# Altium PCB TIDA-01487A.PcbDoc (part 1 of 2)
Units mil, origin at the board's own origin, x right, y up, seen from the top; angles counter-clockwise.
Board outline 3500 x 2800 mil, 4 copper layers (Top Layer, GND, VDD, Bottom Layer), stack 61.6 mil thick; 82 components, 45 nets, 239 pads, 112 vias.
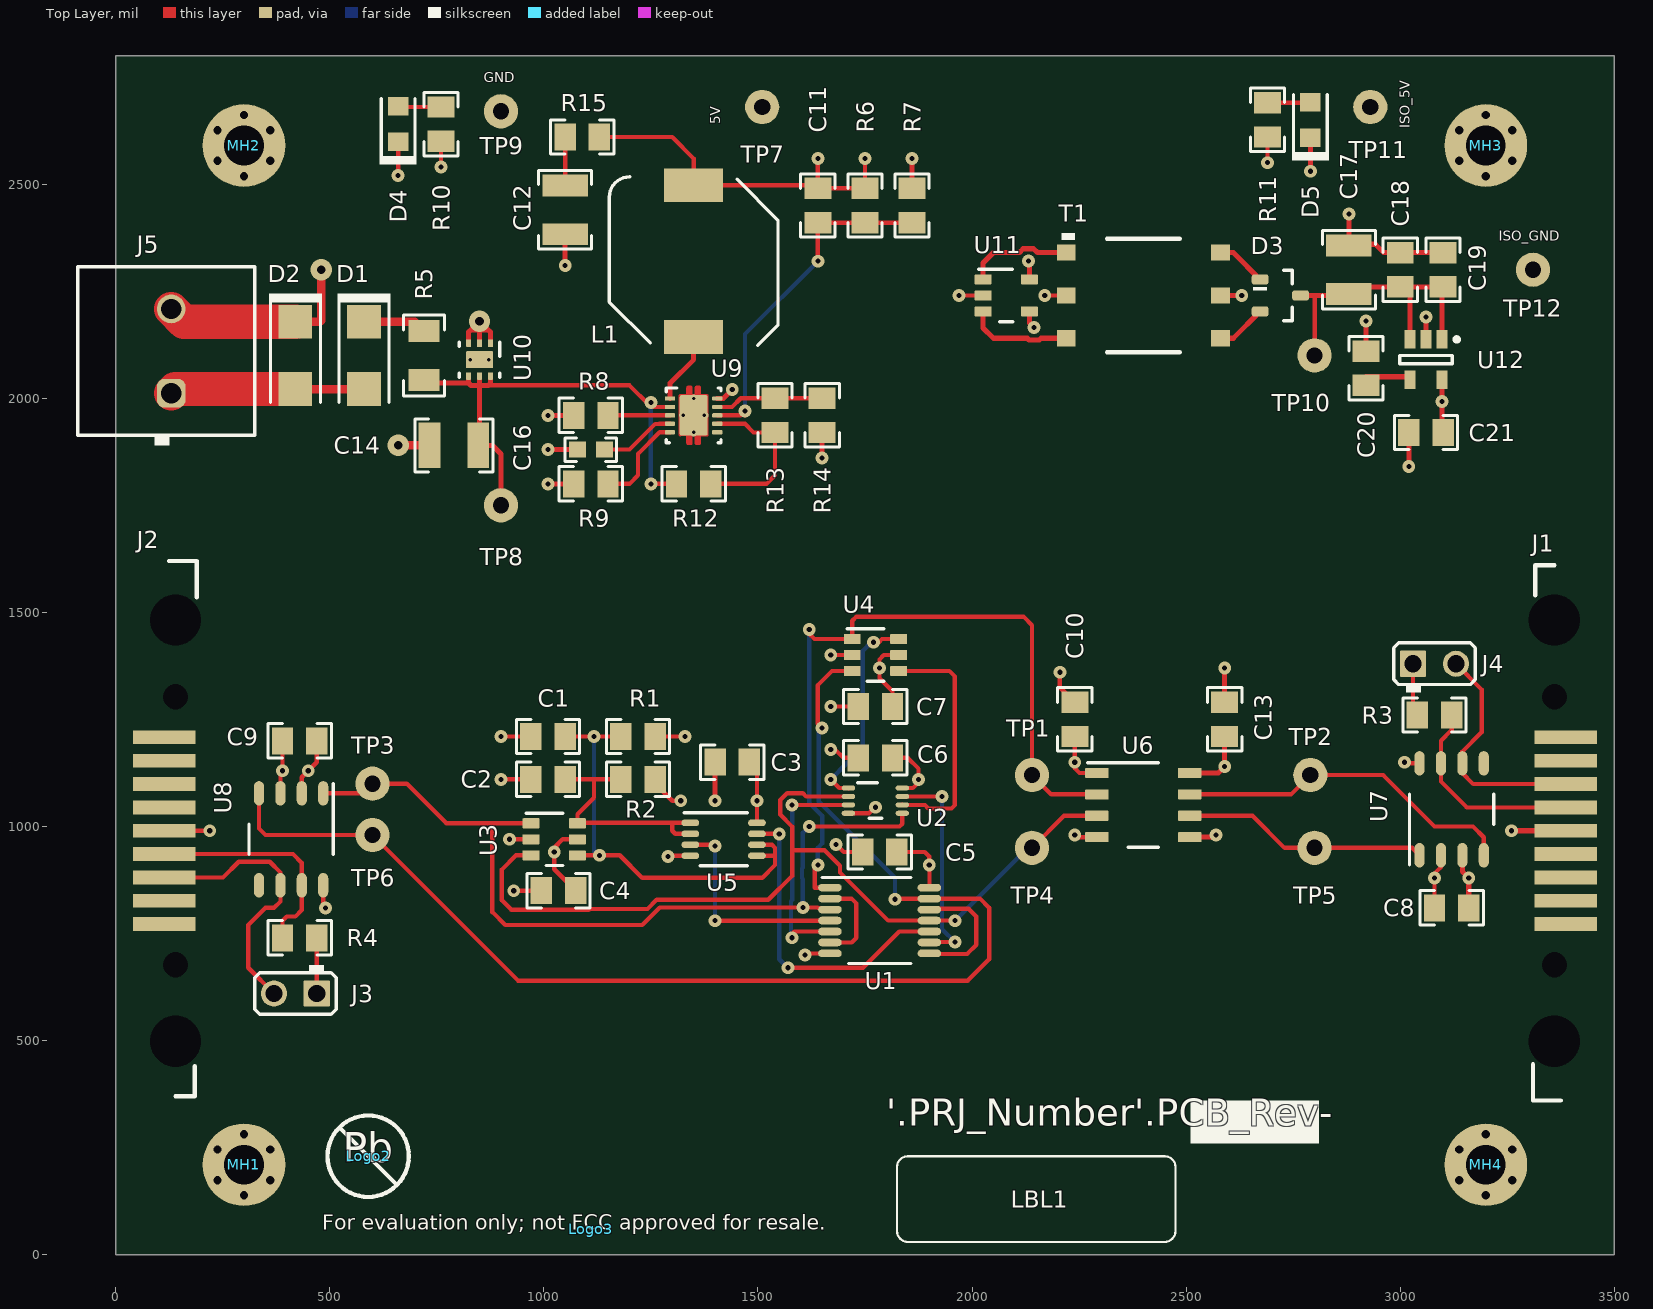
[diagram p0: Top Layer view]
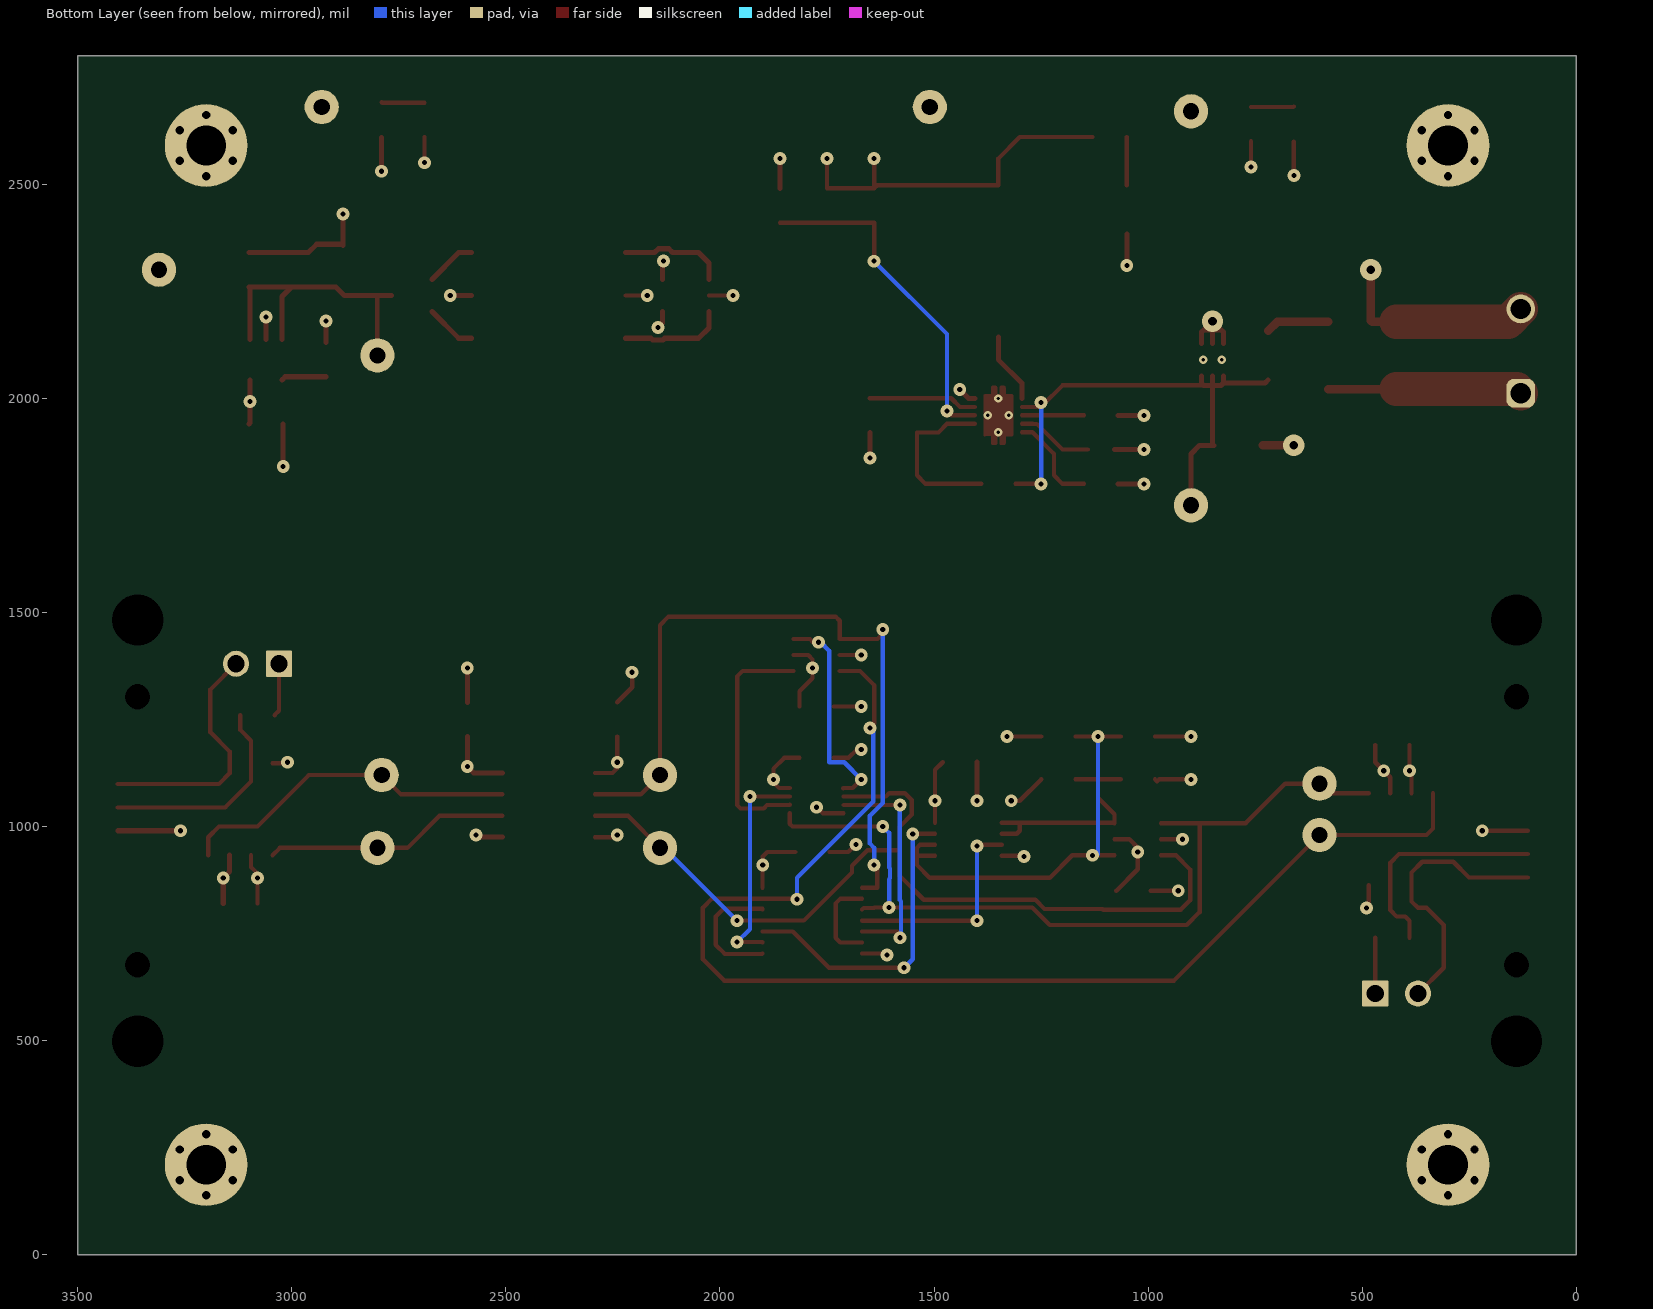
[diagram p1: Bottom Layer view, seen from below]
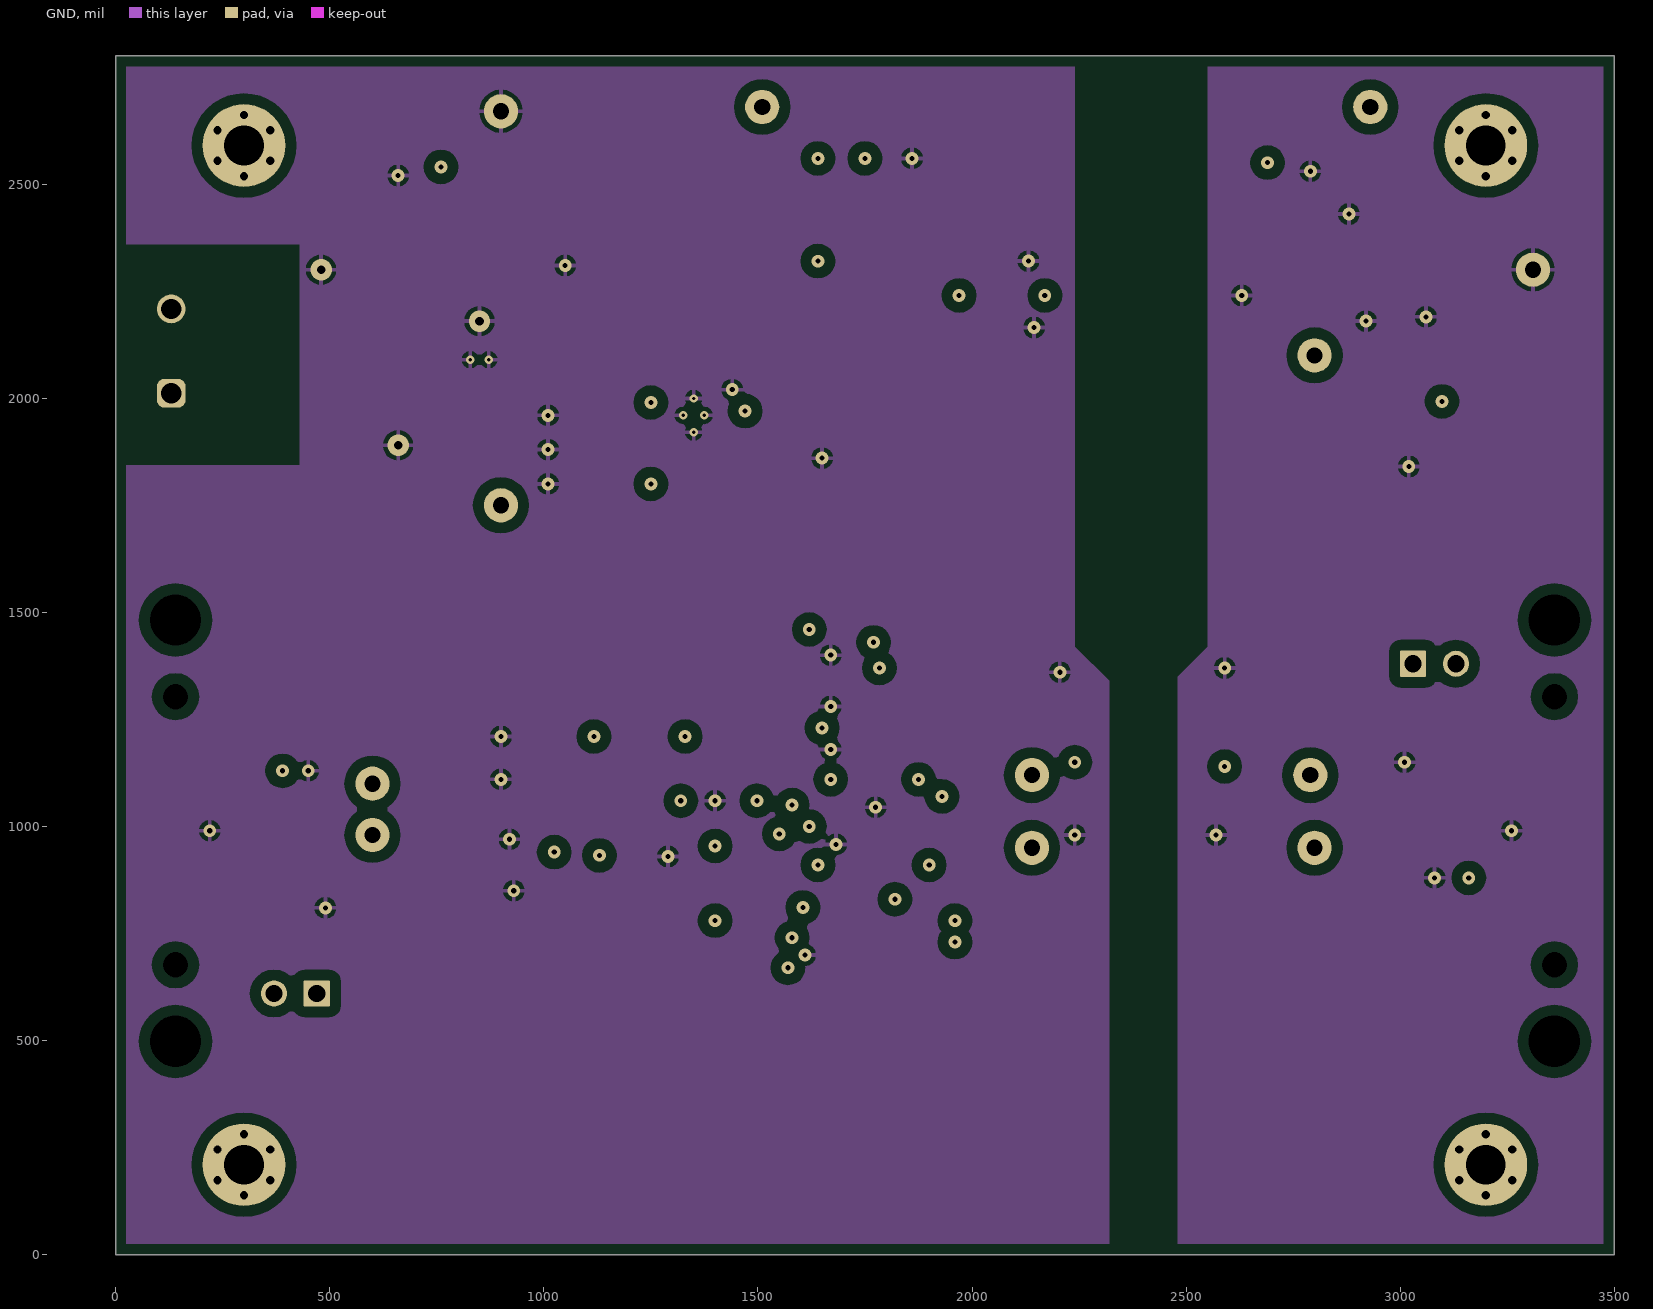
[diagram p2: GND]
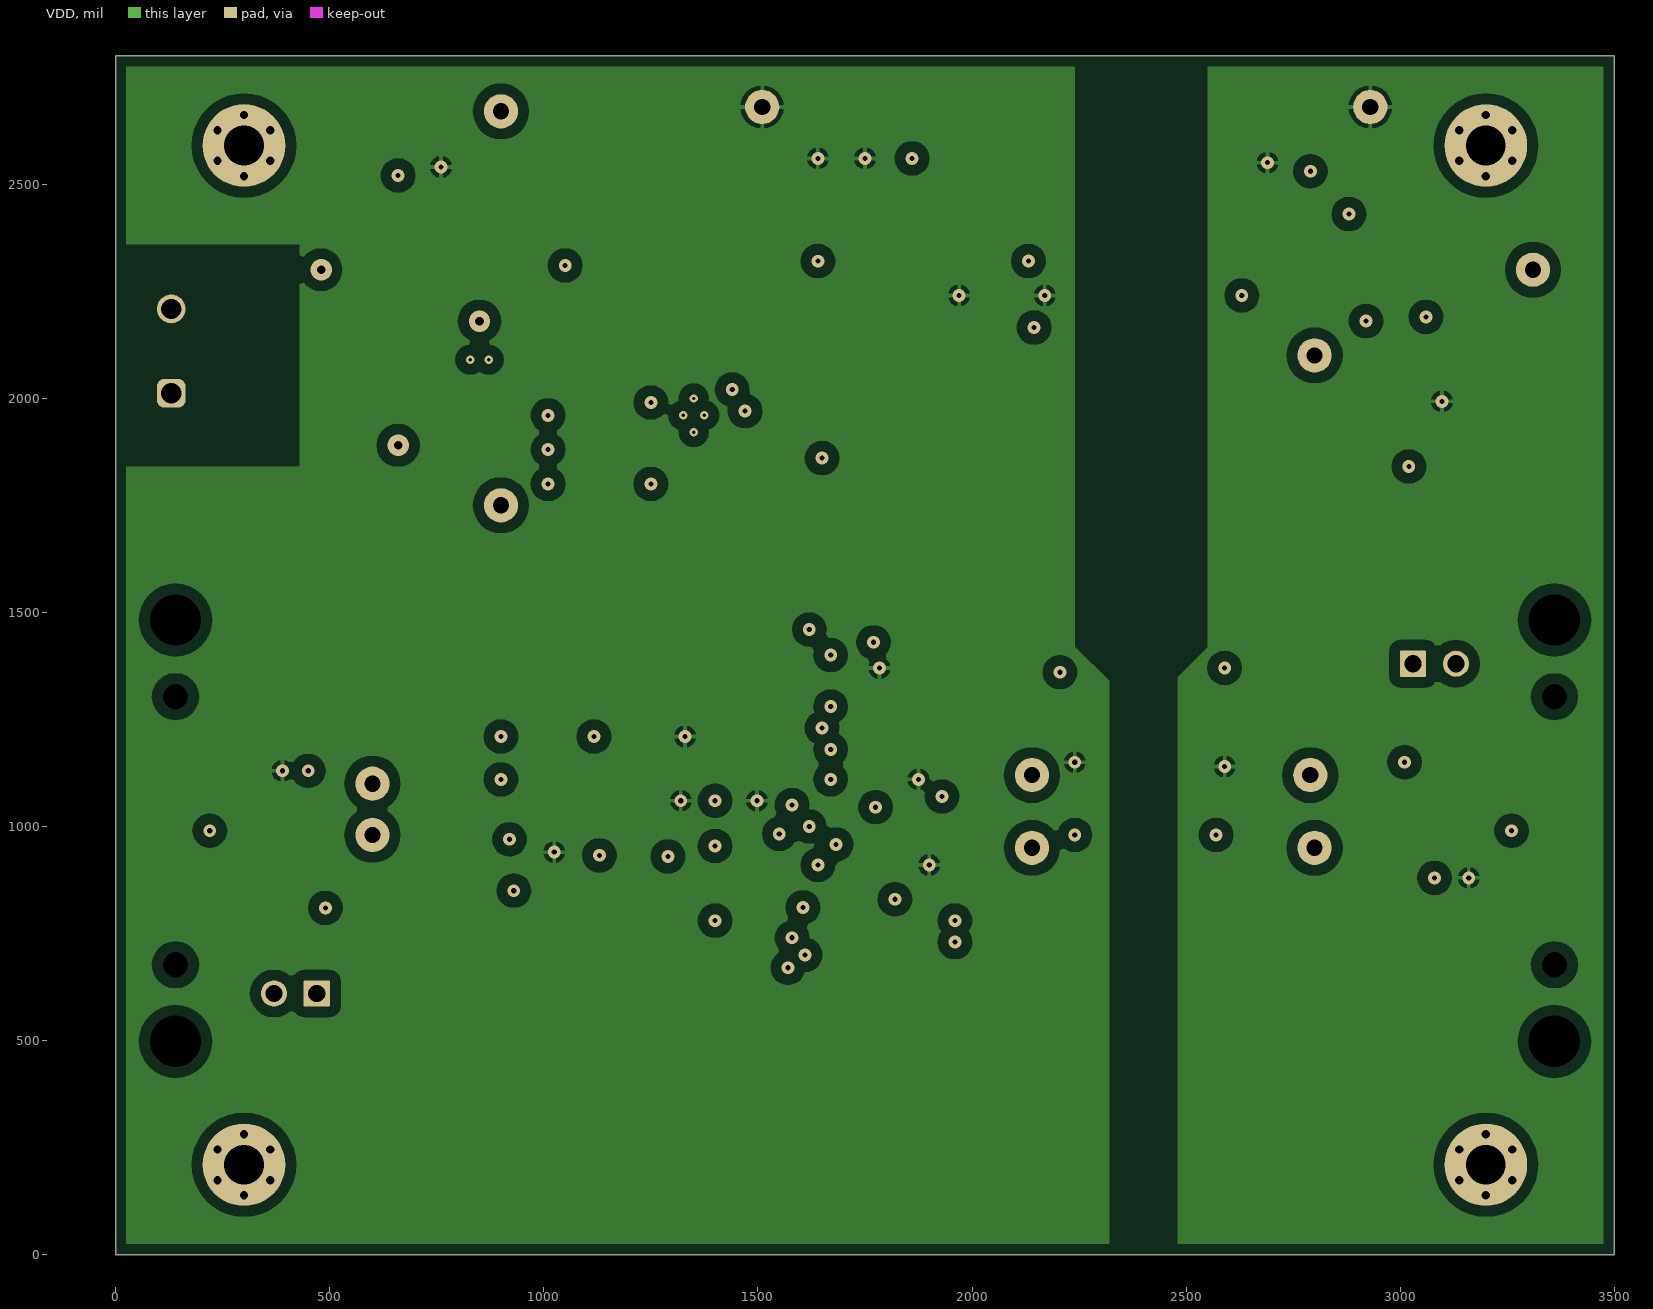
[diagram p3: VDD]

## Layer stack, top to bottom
Top Solder: solder mask 0.4, Solder Resist, Dk 3.5
Top Layer: signal copper 1.4
Dielectric1: core 8, FR-4, Dk 4.8
GND: signal copper 1.4
Dielectric 2: dielectric 40, FR-4, Dk 4.2
VDD: signal copper 1.4
Dielectric 3: dielectric 8, Dk 4.2
Bottom Layer: signal copper 1.4
Bottom Solder: solder mask 0.4, Solder Resist, Dk 3.5

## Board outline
0,0 3500,0 3500,430 3500,860 3500,1720 3500,2800 0,2800

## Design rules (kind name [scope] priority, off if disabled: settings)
AcuteAngle [All] p1: minimum=4.50000000000000E+0001 checktracksonly=FALSE
AssemblyTestPointUsage [All] p1: valid=2
BoardOutlineClearance BoardOutlineClearance_MountingHoles [OnCopper and InComponentClass('Mounting Holes')] p1: gap=40 ignorepadtopadclearanceinfootprint=FALSE
BoardOutlineClearance BoardOutlineClearance_Poly [OnCopper and IsPoly] p2: gap=25 ignorepadtopadclearanceinfootprint=FALSE
BoardOutlineClearance [OnCopper and Not InComponentClass('Logo') and not InComponentClass('FiducialMark') and not InRegion(1000,500,4000,800) and not InPoly] p3: gap=40 ignorepadtopadclearanceinfootprint=FALSE
Clearance Clearance_Keepouts [((IsTrack Or IsArc) And Not InPoly) And IsFree and IsKeepOut vs ((IsTrack Or IsArc) And Not InPoly) And IsFree and IsKeepOut] p1: gap=0 ignorepadtopadclearanceinfootprint=FALSE
Clearance Clearance_Poly [InPolygon] p2: gap=25 ignorepadtopadclearanceinfootprint=FALSE except(0: Arc-Hole Track-Hole SMDPad-Hole THPad-Hole Via-Hole Fill-Hole Poly-Hole Region-Hole Text-Hole)
Clearance [All] p3: gap=7.87 ignorepadtopadclearanceinfootprint=FALSE except(0: Arc-Hole Track-Hole SMDPad-Hole THPad-Hole Via-Hole Fill-Hole Poly-Hole Region-Hole Text-Hole)
ComponentClearance ComponentClearance_MountingHoles_FiducialMarks [InComponentClass('Mounting Holes') vs InComponentClass('FiducialMark')] p1: gap=50 collisioncheckmode=3 verticalgap=10 showdistances=FALSE
ComponentClearance ComponentClearance_Shunt [InComponentClass('Header') vs InComponentClass('Shunt')] p2: gap=0 collisioncheckmode=3 verticalgap=0 showdistances=FALSE
ComponentClearance ComponentClearance_Logo [InComponentClass('Logo')] p3: gap=50 collisioncheckmode=3 verticalgap=10 showdistances=FALSE
ComponentClearance ComponentClearance_ScrewToNut [(HasFootprint('NY PMS 440 0025 PH')) vs (HasFootprint('Keystone_1902C'))] p4: gap=5 collisioncheckmode=3 verticalgap=10 showdistances=FALSE
ComponentClearance ComponentClearance_MountingHoles [InComponentClass('Mounting Holes')] p5: gap=250 collisioncheckmode=3 verticalgap=100000 showdistances=FALSE
ComponentClearance ComponentClearance_SmallPassives [HasFootprint('0201*') or HasFootprint('0402*') or HasFootprint('0508') or HasFootprint('0603*') or HasFootprint('0612') or HasFootprint('0805*') or HasFootprint('0815*') or HasFootprint('0830*') or HasFootprint('1206*') or HasFootprint('1210*') or HasFootprint('1808*') or HasFootprint('1812*') or HasFootprint('1825*') or HasFootprint('2010*') or HasFootprint('2220*') or HasFootprint('2225*') or HasFootprint('2512*') or HasFootprint('2728*') or HasFootprint('3518*') vs HasFootprint('0201*') or HasFootprint('0402*') or HasFootprint('0508') or HasFootprint('0603*') or HasFootprint('0612') or HasFootprint('0805*') or HasFootprint('0815*') or HasFootprint('0830*') or HasFootprint('1206*') or HasFootprint('1210*') or HasFootprint('1808*') or HasFootprint('1812*') or HasFootprint('1825*') or HasFootprint('2010*') or HasFootprint('2220*') or HasFootprint('2225*') or HasFootprint('2512*') or HasFootprint('2728*') or HasFootprint('3518*')] p6: gap=14.96 collisioncheckmode=3 verticalgap=10 showdistances=FALSE
ComponentClearance ComponentClearance_THtoSMT [IsThruComponent vs IsSMTComponent] p7: gap=40 collisioncheckmode=3 verticalgap=30 showdistances=FALSE
ComponentClearance ComponentClearance_THtoTH [IsThruComponent vs IsThruComponent] p8: gap=30 collisioncheckmode=3 verticalgap=30 showdistances=FALSE
ComponentClearance [All] p9: gap=30 collisioncheckmode=3 verticalgap=10 showdistances=FALSE
DiffPairsRouting [All] p1: maxlimit=100 minlimit=10 mostfreqgap=10 toplayer_minwidth=15 toplayer_maxwidth=15 toplayer_prefwidth=15 midlayer1_minwidth=15 midlayer1_maxwidth=15 midlayer1_prefwidth=15 midlayer2_minwidth=15 midlayer2_maxwidth=15 midlayer2_prefwidth=15 bottomlayer_minwidth=15 bottomlayer_maxwidth=15 bottomlayer_prefwidth=15 maxuncoupledlength=1000
FabricationTestPointUsage TestPointUsage [All] p1: valid=2 allowmultiple=FALSE
FabricationTestpoint Testpoint [All] p1: side=3 testpointundercomponent=TRUE minsize=40 maxsize=100 preferedsize=60 minholesize=0 maxholesize=40 preferedholesize=32 testpointgrid=1 allowsidetop=TRUE allowsidebottom=TRUE usegrid=TRUE gridtolerance=0.01
FanoutControl Fanout_LCC [IsLCC] p1: bgadir=Out bgaviamode=Centered fanoutstyle=Auto fanoutdirection=Alternating viagrid=1 // Fanout_LCC (Default Rule)
FanoutControl Fanout_BGA [IsBGA] p2: bgadir=Out bgaviamode=Centered fanoutstyle=Auto fanoutdirection=Alternating viagrid=1 // Fanout_BGA (Default Rule)
FanoutControl Fanout_Default [All] p4: bgadir=Out bgaviamode=Centered fanoutstyle=Auto fanoutdirection=Alternating viagrid=1 // Fanout_Default (Default Rule)
FanoutControl Fanout_Small [(CompPinCount < 5)] p5: bgadir=Out bgaviamode=Centered fanoutstyle=Auto fanoutdirection=OutThenIn viagrid=1 // Fanout_Small (Default Rule)
HoleSize [All] p1: absolutevalues=TRUE maxlimit=251 minlimit=7.87 maxpercent=80.000 minpercent=20.000
MinimumAnnularRing MinimumAnnularRing_ThermalPadVias [IsVia and InAnyComponent] p1: minimumring=5.91
MinimumAnnularRing [All] p2: minimumring=8
MinimumSolderMaskSliver MinimumSolderMaskSliver_Logo [InComponentClass('Logo') vs InComponentClass('Logo')] p1: minsoldermaskwidth=0.7
MinimumSolderMaskSliver [All] p2: minsoldermaskwidth=3.94
PlaneConnect [All] p1: planeconnectstyle=Relief reliefexpansion=10 reliefentries=4 reliefconductorwidth=10 reliefairgap=10
PolygonConnect [All] p1: connectstyle=Relief reliefconductorwidth=10 reliefentries=4 polygonreliefangle="90 Angle" airgapwidth=10
RoutingVias ThermalPadVias [IsVia and InAnyComponent] p1: holewidth=7.87 width=20 viastyle="Through Hole" minholewidth=7.87 minwidth=10 maxholewidth=20 maxwidth=40
RoutingVias [All] p2: holewidth=12 width=24 viastyle="Through Hole" minholewidth=12 minwidth=19 maxholewidth=50 maxwidth=100
ShortCircuit ShortCircuit_MH [name like 'MH*' vs IsVia] p1: allowed=TRUE
ShortCircuit ShortCircuit_1 [All] p2: allowed=FALSE
SilkToBoardRegionClearance [Not ((IsComment or IsDesignator) And (Hide <> 'False')) and not InRegion(1000,500,4000,800)] p1:
SilkToSilkClearance SilkToSilkClearance_Pb-FreeLogo [(HasFootprint('Pb-Free_Overlay_Medium') OR HasFootprint('Pb-Free_Overlay_Small')) vs (HasFootprint('Pb-Free_Overlay_Medium') OR HasFootprint('Pb-Free_Overlay_Small'))] p1: silktosilkclearance=0
SilkToSilkClearance [All] p2: silktosilkclearance=4
SilkToSolderMaskClearance SilkToComponentPadClearance [(IsPad or IsFill or IsRegion) and InAnycomponent] p1: minsilkscreentomaskgap=5 clearancetoexposedcopper=TRUE
SilkToSolderMaskClearance "Silk to Solder Mask Opening" [All] p2: minsilkscreentomaskgap=4 clearancetoexposedcopper=FALSE
SolderMaskExpansion [All] p1: expansion=1.97
Width [All] p1: maxlimit=100 minlimit=6 preferedwidth=10 checkconnectedcopper=TRUE
14 further rules are at their usual default settings.

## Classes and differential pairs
component class TIDA-01487A_Power: C11 C12 C14 C16 C17 C18 C19 C20 C21 D1 D2 D3 D4 D5 J5 L1 R5 R6 R7 R8 R9 R10 R11 R12 R13 R14 R15 T1 TP7 TP8 TP9 TP10 TP11 TP12 U9 U10 U11 U12
component class TIDA-01487A_CanFdInterface: C8 C9 C10 C13 J1 J2 J3 J4 R3 R4 TP1 TP2 TP3 TP4 TP5 TP6 U6 U7 U8
component class TIDA-01487A_BusArbitrationLogic: C1 C2 C3 C4 C5 C6 C7 R1 R2 U1 U2 U3 U4 U5
component class Header: J3 J4
component class Label: LBL1
component class AssemblyNote: ZZ1 ZZ2 ZZ3 ZZ4
component class TIDA-01487A_EVM_Hardware: LBL1 Logo2 Logo3 MH1 MH2 MH3 MH4 ZZ1 ZZ2 ZZ3 ZZ4

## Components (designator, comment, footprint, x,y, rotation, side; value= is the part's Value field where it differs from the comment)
C1 "GQM2195C1H470JB01D" 0805_HV 1010,1210 r0 top value=47pF
C2 "GQM2195C1H470JB01D" 0805_HV 1010,1110 r0 top value=47pF
C3 "ECPU1C104MA5" 0805_HV 1440,1150 r180 top value=0.1uF
C4 "ECPU1C104MA5" 0805_HV 1034.41,850 r180 top value=0.1uF
C5 "ECPU1C104MA5" 0805_HV 1784.41,940.31 r180 top value=0.1uF
C6 "ECPU1C104MA5" 0805_HV 1774.41,1160.31 r180 top value=0.1uF
C7 "ECPU1C104MA5" 0805_HV 1774.41,1280.31 r180 top value=0.1uF
C8 "ECPU1C104MA5" 0805_HV 3120,810 r180 top value=0.1uF
C9 "ECPU1C104MA5" 0805_HV 430,1200 r0 top value=0.1uF
C10 "ECPU1C104MA5" 0805_HV 2240,1250 r90 top value=0.1uF
C11 "GRM2165C1H101JA01D" 0805_HV 1640,2450 r270 top value=100pF
C12 "GCM32ER70J476KE19L" 1210_270 1050,2440 r270 top value=47uF
C13 "ECPU1C104MA5" 0805_HV 2590,1250 r90 top value=0.1uF
C14 "GRM32ER72A225KA35L" 1210_270 790,1890 r180 top value=2.2uF
C16 "GRM188R71H333KA61D" 0603 1110,1880 r180 top value=0.033uF
C17 "GRM32ER71K475KE14L" 1210_270 2880,2300 r90 top value=4.7uF
C18 "ECPU1C104MA5" 0805_HV 3000,2300 r90 top value=0.1uF
C19 "EMK212B7105KG-T" 0805_HV 3100,2300 r90 top value=1uF
C20 "GRM216R71H103KA01D" 0805_HV 2920,2070 r90 top value=0.01uF
C21 "EMK212B7105KG-T" 0805_HV 3060,1920 r180 top value=1uF
D1 "CD214A-B1100LF" SMA 580,2100 r270 top value=100V
D2 "SMAJ36CA" SMA 420,2100 r270 top value=36V
D3 "BAT54C-7-F" SOT-23 2720,2240 r0 top value=30V
D4 "150080GS75000" WL-SMCW_Green_0805 660,2640 r90 top value=Green
D5 "150080GS75000" WL-SMCW_Green_0805 2790,2650 r90 top value=Green
J1 "190-009-263R001" NORCOMP_190-009-263R001 3360,990 r270 top
J2 "190-009-263R001" NORCOMP_190-009-263R001 140,990 r90 top
J3 "HB3902U" Foxconn_HB3902U 420,610 r180 top
J4 "HB3902U" Foxconn_HB3902U 3080,1380 r0 top
J5 "1792863" Phoenix_1792863 130,2110 r90 top
L1 "7447714151" WE-PD_1050 1350,2320 r90 top value=150uH
LBL1 "Size: 0.65\" x 0.20 \"" Label_650x200 2150,130 r0 top
Logo2 "Pb-Free Symbol" Pb-Free_Overlay_Medium 590,230 r0 top
Logo3 "FCC disclaimer" FCC_disclaimer 1110,60 r0 top
MH1 "MTG_Pads" MTGP_2-48_PanHead 300,210 r0 top
MH2 "MTG_Pads" MTGP_2-48_PanHead 300,2590 r0 top
MH3 "MTG_Pads" MTGP_2-48_PanHead 3200,2590 r0 top
MH4 "MTG_Pads" MTGP_2-48_PanHead 3200,210 r0 top
R1 "CRCW08054K42FKEA" 0805_HV 1220,1210 r0 top value=4.42k
R2 "CRCW08054K42FKEA" 0805_HV 1220,1110 r0 top value=4.42k
R3 "CRCW0805120RJNEA" 0805_HV 3080,1260 r0 top value=120
R4 "CRCW0805120RJNEA" 0805_HV 430,740 r180 top value=120
R5 "ERJ-8ENF10R0V" 1206 720,2100 r270 top value=10.0
R6 "CRCW0805309KFKEA" 0805_HV 1750,2450 r90 top value=309k
R7 "CRCW0805100KFKEA" 0805_HV 1860,2450 r270 top value=100k
R8 "CRCW08050000Z0EA" 0805_HV 1110,1960 r0 top value=0
R9 "CRCW0805309KFKEA" 0805_HV 1110,1800 r0 top value=309k
R10 "CRCW08052K70JNEA" 0805_HV 760,2640 r270 top value=2.7k
R11 "CRCW08052K70JNEA" 0805_HV 2690,2650 r270 top value=2.7k
R12 "CRCW080510M0JNEA" 0805_HV 1350,1800 r0 top value=10Meg
R13 "CRCW08050000Z0EA" 0805_HV 1540,1960 r270 top value=0
R14 "CRCW08050000Z0EA" 0805_HV 1650,1960 r90 top value=0
R15 "CRM0805-FX-R100ELF" 0805_HV 1090,2610 r0 top value=0.1
T1 "760390014" Wurth_760390013 2400,2240 r0 top value=475uH
TP1 "TESTPOINT" TESTPOINT 2140,1120 r0 top
TP2 "TESTPOINT" TESTPOINT 2790,1120 r0 top
TP3 "TESTPOINT" TESTPOINT 600,1100 r0 top
TP4 "TESTPOINT" TESTPOINT 2140,950 r0 top
TP5 "TESTPOINT" TESTPOINT 2800,950 r0 top
TP6 "TESTPOINT" TESTPOINT 600,980 r0 top
TP7 "TESTPOINT" TESTPOINT 1510,2680 r0 top
TP8 "TESTPOINT" TESTPOINT 900,1750 r0 top
TP9 "TESTPOINT" TESTPOINT 900,2670 r0 top
TP10 "TESTPOINT" TESTPOINT 2800,2100 r0 top
TP11 "TESTPOINT" TESTPOINT 2930,2680 r0 top
TP12 "TESTPOINT" TESTPOINT 3310,2300 r0 top
U1 "SN74LV32APWR" PW0014A_N 1784.41,780.31 r0 top
U2 "SN74LVC2G08DCUR" DCU0008A_N 1774.41,1060.31 r0 top
U3 "SN74LVC2G07DBVR" DBV0006A_N 1024.41,970 r0 top
U4 "SN74LVC2G04DBVR" DBV0006A_N 1774.41,1400.31 r0 top
U5 "SN74LVC2G132DCTR" DCT0008A_N 1420,970 r0 top
U6 "ISO7721DR" D0008B_HV 2400,1050 r0 top
U7 "TCAN1042HDRQ1" D0008A_N 3120,1040 r90 top
U8 "TCAN1042HDRQ1" D0008A_N 410,970 r270 top
U9 "LM5166DRCR" DRC0010J 1350,1960 r0 top
U10 "TVS3300DRVR" DRV0006A 850,2090 r270 top
U11 "SN6501DBVR" DBV0005A_N 2080,2240 r0 top
U12 "LP3985IM5X-5.0" MF05A_N 3060,2090 r270 top
ZZ1 "This Assembly Note is for PCB labels only" AssemblyNoteLabel 185,3938 r0 top
ZZ2 "This Assembly Note will show in the PcbDoc and associated outputs" AssemblyNote 185,3829.11 r0 top
ZZ3 "This Assembly Note will show in the PcbDoc and associated outputs" AssemblyNote 185,3740.56 r0 top
ZZ4 "This Assembly Note will show in the PcbDoc and associated outputs" AssemblyNote 185,3652 r0 top

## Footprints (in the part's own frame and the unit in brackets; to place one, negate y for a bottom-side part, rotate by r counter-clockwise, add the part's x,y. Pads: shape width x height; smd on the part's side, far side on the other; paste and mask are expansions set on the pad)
0603 [mm] "0603 from SM-752 data"
  rect 1x0.95 smd: 1(-0.8,0) 2(0.8,0)
  silkscreen extent -1.52,-0.69 1.52,0.69, body extent -0.87,-0.47 0.87,0.47, height 1
0805_HV [mil] "0805 with 30mil clearance between pads"
  rect 50x63 smd: 1(-40,0) 2(40,0)
  silkscreen extent -74,-40 74,40, body extent -43,-29 43,29, height 57
1206 [mm] "1206 from SM-752 data"
  rect 1.3x1.85 smd: 1(-1.45,0) 2(1.45,0)
  silkscreen extent -2.4,-1.21 2.4,1.21, body extent -1.7,-0.9 1.7,0.9, height 1.35
1210_270 [mm] "1210"
  rect 1.3x2.7 smd: 1(-1.45,0) 2(1.45,0)
  silkscreen extent -2.32,-1.57 2.32,1.57, body extent -1.7,-1.35 1.7,1.35, height 2.7
AssemblyNote [mil] "Assembly Note"
AssemblyNoteLabel [mil] "Assembly Note for PCB Labels"
D0008A_N [mm] "SOIC, 8-Leads, Body 4.9x3.9mm, Pitch 1.27mm, IPC Medium Density"
  oval 1.45x0.6 smd: 1(-2.725,1.905) 2(-2.725,0.635) 3(-2.725,-0.635) 4(-2.725,-1.905) 5(2.725,-1.905) 6(2.725,-0.635) 7(2.725,0.635) 8(2.725,1.905)
  silkscreen extent -3.3,-2.5 0.9,2.5, body extent -3,-2.45 3,2.45, height 1.63
D0008B_HV [mm] "SOIC, 8-Leads, Body 4.9x3.9mm, Pitch 1.27mm, HV / Isolation option"
  rrect17% 1.4x0.6 smd: 1(-2.75,1.905) 2(-2.75,0.635) 3(-2.75,-0.635) 4(-2.75,-1.905) 5(2.75,-1.905) 6(2.75,-0.635) 7(2.75,0.635) 8(2.75,1.905)
  silkscreen extent -3.3,-2.5 0.9,2.5, body extent -3,-2.45 3,2.45, height 1.63
DBV0005A_N [mm] "SOT23, 5-Leads, Body 2.9x1.6mm, Pitch 0.95mm, Lead Span 2.8mm, IPC Medium Density"
  rrect17% 1x0.6 smd: 1(-1.375,0.95) 2(-1.375,0) 3(-1.375,-0.95) 4(1.375,-0.95) 5(1.375,0.95)
  silkscreen extent -1.63,-1.55 0.38,1.55, body extent -1.42,-1.46 1.42,1.46, height 1.09
DBV0006A_N [mm] "SOT23, 6-Leads, Body 2.9x1.6mm, Pitch 0.95mm, Lead Span 2.8mm, IPC Medium Density"
  rrect17% 1x0.6 smd: 1(-1.375,0.95) 2(-1.375,0) 3(-1.375,-0.95) 4(1.375,-0.95) 5(1.375,0) 6(1.375,0.95)
  silkscreen extent -1.68,-1.55 0.5,1.55, body extent -1.42,-1.46 1.42,1.46, height 1.12
DCT0008A_N [mm] "TSOP, 8-Leads, Body 3x2.8mm, Pitch 0.65mm, IPC Medium Density"
  oval 1.05x0.4 smd: 1(-1.975,0.975) 2(-1.975,0.325) 3(-1.975,-0.325) 4(-1.975,-0.975) 5(1.975,-0.975) 6(1.975,-0.325) 7(1.975,0.325) 8(1.975,0.975)
  silkscreen extent -2.32,-1.57 1.4,1.58, body extent -2.01,-1.47 2.01,1.48, height 1.3
DCU0008A_N [mm] "TSSOP, 8-Leads, Body 2x2.3mm, Pitch 0.5mm, IPC Medium Density"
  oval 0.8x0.3 smd: 1(-1.6,0.75) 2(-1.6,0.25) 3(-1.6,-0.25) 4(-1.6,-0.75) 5(1.6,-0.75) 6(1.6,-0.25) 7(1.6,0.25) 8(1.6,0.75)
  silkscreen extent -1.05,-1.05 0.38,1.05, body extent -1.56,-1 1.56,1, height 0.9
DRC0010J [mm] "SON, 10-Leads, Body 3x3mm, Pitch 0.5mm, Thermal Pad 2.4x1.65mm, TI Recommended"
  rrect40% 0.6x0.25 smd: 1(-1.4,1) 2(-1.4,0.5) 3(-1.4,0) 4(-1.4,-0.5) 5(-1.4,-1) 6(1.4,-1) 7(1.4,-0.5) 8(1.4,0) 9(1.4,0.5) 10(1.4,1)
  rrect40% 0.25x0.34 on Top Paste: 11(-0.25,-1.53) 11(-0.25,1.53) 11(0.25,-1.53) 11(0.25,1.53)
  rrect9% 1.5x1.06 on Top Paste: 11(0,-0.63) 11(0,0.63)
  rrect12% 1.65x2.4 smd paste-1 mask-2: 11(0,0)
  Top Layer region: -0.775,-1.25 -0.425,-1.25 -0.425,-1.65 -0.417,-1.688 -0.396,-1.721 -0.363,-1.742 -0.325,-1.75 -0.325,-1.75 -0.325,-1.75 -0.175,-1.75 -0.175,-1.75 -0.137,-1.742 -0.104,-1.721 -0.083,-1.688 -0.075,-1.65 -0.075,-1.65 -0.075,-1.25 0.075,-1.25 0.075,-1.65 0.083,-1.688 0.104,-1.721 0.137,-1.742 0.175,-1.75 0.175,-1.75 0.175,-1.75 0.325,-1.75 0.325,-1.75 0.363,-1.742 0.396,-1.721 0.417,-1.688 0.425,-1.65 0.425,-1.65 0.425,-1.25 0.775,-1.25 0.813,-1.242 0.846,-1.221 0.867,-1.188 0.875,-1.15 0.875,-1.15 0.875,1.15 0.867,1.188 0.846,1.221 0.813,1.242 0.775,1.25 0.775,1.25 0.425,1.25 0.425,1.65 0.417,1.688 0.396,1.721 0.363,1.742 0.325,1.75 0.325,1.75 0.175,1.75 0.137,1.742 0.104,1.721 0.083,1.688 0.075,1.65 0.075,1.65 0.075,1.25 -0.075,1.25 -0.075,1.65 -0.083,1.688 -0.104,1.721 -0.137,1.742 -0.175,1.75 -0.175,1.75 -0.325,1.75 -0.363,1.742 -0.396,1.721 -0.417,1.688 -0.425,1.65 -0.425,1.65 -0.425,1.25 -0.775,1.25 -0.813,1.242 -0.846,1.221 -0.867,1.188 -0.875,1.15 -0.875,1.15 -0.875,-1.15 -0.867,-1.188 -0.846,-1.221 -0.813,-1.242 -0.775,-1.25
  silkscreen extent -1.63,-1.63 1.63,1.63, body extent -1.5,-1.5 1.5,1.5, height 0.77
DRV0006A [mm] "SON, 6-Leads, Body 2x2mm, Pitch 0.65mm, Thermal Pad 1.6x1mm, TI Recommended"
  rrect33% 0.45x0.3 smd: 1(-0.975,0.65) 2(-0.975,0) 3(-0.975,-0.65) 4(0.975,-0.65) 5(0.975,0) 6(0.975,0.65)
  rrect14% 1x0.7 on Top Paste: 7(0,0.45) 7(0,-0.45)
  rrect10% 1x1.6 smd paste-0.5: 7(0,0)
  silkscreen extent -1.05,-1.2 1.05,1.2, body extent -1.05,-1.05 1.05,1.05, height 0.81
FCC_disclaimer [mil]
Foxconn_HB3902U [mm] "Header, 2.54mm, 2x1, TH"
  rrect6% 1.55x1.55 hole 1.02: 1(-1.27,0)
  round 1.55 hole 1.02: 2(1.27,0)
  silkscreen extent -2.42,-1.7 2.41,1.23, body extent -2.41,-1.23 2.42,1.24, height 8.38
Label_650x200 [mil] "Thermal Transfer Label"
  silkscreen extent -325,-100 325,100, body extent -325,-100 325,100, height 1
MF05A_N [mm] "SOT23, 5-Leads, Body 2.9x1.6mm, Pitch 0.95mm, Lead Span 2.8mm, IPC Medium Density"
  rect 1.1x0.65 smd: 1(-1.2,0.95) 2(-1.2,0) 3(-1.2,-0.95) 4(1.2,-0.95) 5(1.2,0.95)
  silkscreen extent -1.32,-1.55 0.25,1.95, body extent -0.9,-1.55 0.9,1.55, height 1.19
MTGP_2-48_PanHead [mm] "2-48 Mounting Hole, Plated, for Pan Head"
  round 4.9 hole 2.35: 1(0,0)
NORCOMP_190-009-263R001 [mil] "Norcomp"
  rect 32x146 smd: 1(-218,26) 2(-109,26) 3(0,26) 4(109,26) 5(218,26) 6(-163.5,26) 7(-54.5,26) 8(54.5,26) 9(163.5,26)
  round 100 hole 120 unplated: MH(-492,0) MH(492,0)
  round 40 hole 59 unplated: MH(-313,0) MH(313,0)
  silkscreen extent -620,-50 630,15, body extent -593,-28 592,390, height 426
Pb-Free_Overlay_Medium [mil]
  silkscreen extent -95,-95 95,95
Phoenix_1792863 [mm] "Terminal Block, 5mm, 2x1, R/A, TH"
  rrect50% 1.7x1.7 hole 1.2: 1(-2.5,0)
  round 1.7 hole 1.2: 2(2.5,0)
  silkscreen extent -5.6,-4.95 5,5.55, body extent -5,-4.95 5,5.55, height 13.6
PW0014A_N [mm] "TSOP, 14-Leads, Body 5x4.4mm, Pitch 0.65mm, IPC Medium Density"
  oval 1.4x0.45 smd: 1(-2.95,1.95) 2(-2.95,1.3) 3(-2.95,0.65) 4(-2.95,0) 5(-2.95,-0.65) 6(-2.95,-1.3) 7(-2.95,-1.95) 8(2.95,-1.95) 9(2.95,-1.3) 10(2.95,-0.65) 11(2.95,0) 12(2.95,0.65) 13(2.95,1.3) 14(2.95,1.95)
  silkscreen extent -3.4,-2.55 1.85,2.55, body extent -3.21,-2.5 3.21,2.5, height 1
SMA [mm] "Molded Diode, 2-Leads, Body 4.3x2.6mm, IPC Medium Density, based on OnSemi component dimensions and land pattern"
  rect 2x2 smd: 1(-2,0) 2(2,0)
  silkscreen extent -3.66,-1.57 2.79,1.57, body extent -2.6,-1.3 2.6,1.3, height 2.42
SOT-23 [mm] "SOT23, 3-Leads, Body 2.9x1.3mm, Pitch 0.95mm, Lead Span 2.5mm, IPC Medium Density"
  rrect50% 1x0.6 smd: 1(-1.2,0.95) 2(-1.2,-0.95) 3(1.2,0)
  silkscreen extent -1.63,-1.5 0.7,1.5, body extent -1.16,-1.45 1.21,1.45, height 1
TESTPOINT [mil]
  round 80 hole 37.99: 1(0,0)
WE-PD_1050 [mm] "WERTH"
  rect 2x3.5 smd: 1(-4.5,0) 2(4.5,0)
  silkscreen extent -5,-5 5,5, body extent -5,-5 5,5, height 4.75
WL-SMCW_Green_0805 [mm] "SMD, 2-Leads, Body 2x1.25mm"
  rect 1.1x1.2 smd: 1(-1.05,0) 2(1.05,0)
  silkscreen extent -2.4,-1.1 1.5,1.1, body extent -1,-0.62 1,0.63, height 0.7
Wurth_760390013 [mil] "Wurth"
  rect 44x38 smd: 1(-180,100) 2(-180,0) 3(-180,-100) 4(180,-100) 5(180,0) 6(180,100)
  silkscreen extent -190,-132 85,145, body extent -198,-135 198,130, height 166

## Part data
C1 C2: "CAP, CERM, 47 pF, 50 V,+/- 5%, C0G/NP0, 0805", Cap_Case=0805, Manufacturer=MuRata, Supplier Part Number 1=490-3612-1-ND, TempCo=C0G/NP0, Tolerance_%=5, Value2=50V, ValueDisplayed=47pF
C3 C4 C5 C6 C7 C8 C9 C10 C13 C18: "CAP, Film, 0.1 µF, 16 V,+/- 20%, 0805 SMD", Cap_Case=0805, Manufacturer=Panasonic, Supplier Part Number 1=PCF1126CT-ND, Tolerance_%=20, Value2=16V, ValueDisplayed=0.1µF
C11: "CAP, CERM, 100 pF, 50 V,+/- 5%, C0G/NP0, 0805", Cap_Case=0805, Manufacturer=MuRata, Supplier Part Number 1=490-1615-1-ND, TempCo=C0G/NP0, Tolerance_%=5, Value2=50V, ValueDisplayed=100pF
C12: "CAP, CERM, 47 µF, 6.3 V,+/- 10%, X7R, AEC-Q200 Grade 1, 1210", Cap_Case=1210, Manufacturer=MuRata, Supplier Part Number 1=490-4844-1-ND, TempCo=X7R, Tolerance_%=10, Value2=6.3V, ValueDisplayed=47µF
C14: "CAP, CERM, 2.2 µF, 100 V,+/- 10%, X7R, 1210", Cap_Case=1210, Manufacturer=MuRata, Supplier Part Number 1=490-3385-1-ND, TempCo=X7R, Tolerance_%=10, Value1="0.007 ohm", Value2=100V, ValueDisplayed=2.2µF
C16: "CAP, CERM, 0.033 µF, 50 V,+/- 10%, X7R, 0603", Cap_Case=0603, Manufacturer=MuRata, Supplier Part Number 1=490-3286-1-ND, TempCo=X7R, Tolerance_%=10, Value2=50V, ValueDisplayed=0.033µF
C17: "CAP, CERM, 4.7 µF, 80 V,+/- 10%, X7R, 1210", Cap_Case=1210, Manufacturer=MuRata, Supplier Part Number 1=490-9972-1-ND, TempCo=X7R, Tolerance_%=10, Value2=80V, ValueDisplayed=4.7µF
C19 C21: "CAP, CERM, 1 µF, 16 V,+/- 10%, X7R, 0805", Cap_Case=0805, Manufacturer="Taiyo Yuden", Supplier Part Number 1=587-1283-1-ND, TempCo=X7R, Tolerance_%=10, Value2=16V, ValueDisplayed=1µF
C20: "CAP, CERM, 0.01 µF, 50 V,+/- 10%, X7R, 0805", Cap_Case=0805, Manufacturer=MuRata, Supplier Part Number 1=490-1664-1-ND, TempCo=X7R, Tolerance_%=10, Value2=50V, ValueDisplayed=0.01µF
D1: "Diode, Schottky, 100 V, 1 A, SMA", Manufacturer=Bourns, Supplier Part Number 1=652-CD214A-B1100LF, Value1=1A, Value2=0.79V
D2: "Diode, TVS, Bi, 36 V, SMA", Manufacturer=Littelfuse, Power_W=3.3, Supplier Part Number 1=SMAJ36CALFDKR-ND, Value1=3.3W
D3: "Diode, Schottky, 30 V, 0.2 A, SOT-23", Manufacturer="Diodes Inc.", Supplier Part Number 1=BAT54C-FDICT-ND, Value1=0.2A, Value2=0.65V
D4 D5: "LED, Green, SMD", Color=Green, Manufacturer="Wurth Elektronik", Power_TotalModule=0.105, Supplier Part Number 1=732-4983-1-ND, Value1=0.105W, Value2=3.2V
J1 J2: "CONN DB9 FEMALE R/A SOLDER SMD", Manufacturer=NorComp, Supplier Part Number 1=190-09FA-ND
J3 J4: "Header, 2.54mm, 2x1, Gold, TH", Color=Black, Current_A=3, Manufacturer=Foxconn, Voltage_V=500
J5: "Terminal Block, 5mm, 2x1, R/A, TH", Color=Green, Current_A=16, Manufacturer="Phoenix Contact", Supplier Part Number 1=277-2518-ND, Voltage_V=400
L1: "Inductor, Shielded Drum Core, Ferrite, 150 µH, 1.2 A, 0.251 ohm, SMD", Manufacturer="Wurth Elektronik", Supplier Part Number 1=732-2991-1-ND, Value1="0.251 ohm", Value2=1.2A, ValueDisplayed=150µH
LBL1: library part THT-14-423-10, "Thermal Transfer Printable Labels, 0.650\" W x 0.200\" H - 10,000 per roll", Manufacturer=Brady, Supplier Part Number 1=97C5133
Logo2: library part Pb-Free
Logo3: library part FCC_disclaimer, "FCC_disclaimer"
MH1 MH2 MH3 MH4: library part "Mounting Hole (Imperial) with Pads", "PCB Mounting Hole", Manufacturer=Any, PartNumber=N/A
R1 R2: "RES, 4.42 k, 1%, 0.125 W, 0805", Manufacturer=Vishay-Dale, Power_W=0.125, Supplier Part Number 1=541-4.42KCCT-ND, TempCo="100 ppm/C", Tolerance_%=1, Value1=1%, Value2=0.125W, Value_Code=4k42, ValueDisplayed=4.42k
R3 R4: "RES, 120, 5%, 0.125 W, 0805", Manufacturer=Vishay-Dale, Power_W=0.125, Supplier Part Number 1=541-120ACT-ND, TempCo="200 ppm/C", Tolerance_%=5, Value1=5%, Value2=0.125W, Value_Code=120R, ValueDisplayed=120
R5: "RES, 10.0, 1%, 0.25 W, 1206", Manufacturer=Panasonic, Power_W=0.25, Supplier Part Number 1=P10.0FCT-ND, TempCo="100 ppm/C", Tolerance_%=1, Value1=1%, Value2=0.25W, Value_Code=10R0, ValueDisplayed=10.0
R6 R9: "RES, 309 k, 1%, 0.125 W, 0805", Manufacturer=Vishay-Dale, Power_W=0.125, Supplier Part Number 1=541-309KCCT-ND, TempCo="100 ppm/C", Tolerance_%=1, Value1=1%, Value2=0.125W, Value_Code=309k
R7: "RES, 100 k, 1%, 0.125 W, 0805", Manufacturer=Vishay-Dale, Power_W=0.125, Supplier Part Number 1=541-100KCCT-ND, TempCo="100 ppm/C", Tolerance_%=1, Value1=1%, Value2=0.125W, Value_Code=100k
R8 R13 R14: "RES, 0, 5%, 0.125 W, 0805", Manufacturer=Vishay-Dale, Power_W=0.125, Supplier Part Number 1=541-0.0ACT-ND, TempCo="200 ppm/C", Tolerance_%=5, Value1=5%, Value2=0.125W, Value_Code=0000, ValueDisplayed=0
R10 R11: "RES, 2.7 k, 5%, 0.125 W, 0805", Manufacturer=Vishay-Dale, Power_W=0.125, Supplier Part Number 1=541-2.7KACT-ND, TempCo="200 ppm/C", Tolerance_%=5, Value1=5%, Value2=0.125W, Value_Code=2k70, ValueDisplayed=2.7k
R12: "RES, 10 M, 5%, 0.125 W, 0805", Manufacturer=Vishay-Dale, Power_W=0.125, Supplier Part Number 1=541-10MACT-ND, TempCo="200 ppm/C", Tolerance_%=5, Value1=5%, Value2=0.125W, Value_Code=10M0, ValueDisplayed=10M
R15: "RES, 0.1, 1%, 0.25 W, 0805", Manufacturer=Bourns, Power_W=0.25, Supplier Part Number 1=652-CRM0805FXR100ELF, TempCo="150 ppm/C", Tolerance_%=1, Value1=1%, Value2=0.25W, Value_Code=R100, ValueDisplayed=0.1
T1: "Transformer, 475uH, SMT", Manufacturer="Wurth Elektronik", Supplier Part Number 1=732-4458-1-ND, ValueDisplayed=475µH
TP1 TP2 TP3 TP4 TP5 TP6 TP7 TP8 TP9 TP10 TP11 TP12: "TEST POINT.  No entry in BOM."
U1: library part CMP-0050867-1, "Quadruple 2-Input Positive-OR Gates, PW0014A, LARGE T&R", F @ Nom Voltage(Max)(Mhz)=70, Generic Part Number=SN74LV32A, ICC @ Nom Voltage(Max)(mA)=0.02, Manufacturer="Texas Instruments", Operating Temperature Range(C)="-40 to 125,-40 to 85", Rating=Catalog, tpd @ Nom Voltage(Max)(ns)=19,13,8.5, Voltage(Nom)(V)=2.5,3.3,5
U2: "Dual 2-Input Positive-AND Gate, DCU0008A, LARGE T&R", Alternate Manufacturer="Texas Instruments", Alternate PartNumber=Equivalent, F @ Nom Voltage(Max)(Mhz)=150, Generic Part Number=SN74LVC2G08, ICC @ Nom Voltage(Max)(mA)=0.01, Operating Temperature Range(C)="-40 to 125,-40 to 85", Rating=Catalog, Supplier Part Number 1=595-SN74LVC2G08DCUR, tpd @ Nom Voltage(Max)(ns)=9.8,5.8,5.3,4.8, Voltage(Nom)(V)=1.8,2.5,3.3,5
U3: "Dual Buffer/Driver with Open-Drain Output, DBV0006A, LARGE T&R", Alternate Manufacturer="Texas Instruments", Alternate PartNumber=Equivalent, F @ Nom Voltage(Max)(Mhz)=150, Generic Part Number=SN74LVC2G07, ICC @ Nom Voltage(Max)(mA)=0.01, Operating Temperature Range(C)="-40 to 125", Rating=Catalog, Supplier Part Number 1=595-SN74LVC2G07DBVR, tpd @ Nom Voltage(Max)(ns)=8.6,4.4,3.7,2.9, Voltage(Nom)(V)=1.8,2.5,3.3,5
U4: "Dual Inverter, DBV0006A, LARGE T&R", Alternate Manufacturer="Texas Instruments", Alternate PartNumber=Equivalent, F @ Nom Voltage(Max)(Mhz)=150, Generic Part Number=SN74LVC2G04, ICC @ Nom Voltage(Max)(mA)=0.01, Operating Temperature Range(C)="-40 to 125", Rating=Catalog, Supplier Part Number 1=595-SN74LVC2G04DBVR, tpd @ Nom Voltage(Max)(ns)=8,4.9,4.6,3.7, Voltage(Nom)(V)=1.8,2.5,3.3,5
U5: "Dual 2-Input NAND Gate with Schmitt-Trigger Inputs, DCT0008A, LARGE T&R", Alternate Manufacturer="Texas Instruments", Alternate PartNumber=Equivalent, F @ Nom Voltage(Max)(Mhz)=150, Generic Part Number=SN74LVC2G132, ICC @ Nom Voltage(Max)(mA)=0.01, Operating Temperature Range(C)="-40 to 125,-40 to 85", Rating=Catalog, Supplier Part Number 1=595-SN74LVC2G132DCTR, tpd @ Nom Voltage(Max)(ns)=16,7.5,6,5, Voltage(Nom)(V)=1.8,2.5,3.3,5
U6: "High Speed, Robust EMC Dual-Channel Digital Isolator, D0008B (SOIC-8)", Alternate Manufacturer="Texas Instruments", Alternate PartNumber=ISO7721D
U7 U8: "Automotive Fault Protected CAN Transceiver With Flexible Data-Rate, D0008A (SOIC-8)", Alternate Manufacturer="Texas Instruments", Alternate PartNumber=TCAN1042HDQ1
U9: "3V-65V Input, 500mA Synchronous Buck Converter With Ultra-Low Iq, DRC0010J (VSON-10)", Alternate Manufacturer="Texas Instruments", Alternate PartNumber=LM5166DRCT
U10: "33V Precision Surge Protection Clamp, DRV0006A (WSON-6)", Alternate Manufacturer="Texas Instruments", Alternate PartNumber=TVS3300DRVT
U11: "Low-Noise 350 mA, 410 kHz Transformer Driver, DBV0005A (SOT-23-5)", Alternate Manufacturer="Texas Instruments", Alternate PartNumber=SN6501DBVT
U12: "Micropower, 150mA Low-Noise Ultra Low-Dropout CMOS Voltage Regulator, 5-pin SOT-23", Manufacturer="Texas Instruments", PackageTopMarking=LDSB*XTT, PowerWise=N
ZZ1: library part AssemblyNoteLabel
ZZ2 ZZ3 ZZ4: library part AssemblyNote

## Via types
v1: diameter 30, hole 12, Top Layer to Bottom Layer, 79 vias
v2: diameter 39.37, hole 19.68, Top Layer to Bottom Layer, 24 vias
v3: diameter 19.68, hole 7.87, Top Layer to Bottom Layer, 6 vias
v4: diameter 50, hole 20, Top Layer to Bottom Layer, 3 vias

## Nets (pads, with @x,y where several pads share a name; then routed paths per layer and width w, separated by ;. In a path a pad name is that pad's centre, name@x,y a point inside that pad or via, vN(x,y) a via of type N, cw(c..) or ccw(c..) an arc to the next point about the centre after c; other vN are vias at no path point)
5V: C3.1 C4.1 C5.1 C6.1 C7.1 C9.1 C10.1 C11.1 L1.2 R1.2 R2.2 R6.2 R10.2 R15.2 T1.2 TP7.1 U1.14 U2.8 U3.5 U4.5 U5.8 U6.1 U8.3 U11.2 | length 2230.9
  Top Layer w10: U8.3@385,1077.28 385,1125 v1(390,1130) C9.1@390,1190 ; v1(760,2540) R10.2@760,2600 ; C4.1@1074.41,850 1024.41,900 v1(1024.41,940) 1024.41,950.32 1044.09,970 U3.5@1078.54,970 ; R15.2@1130,2610 1300,2610 1350,2560 L1.2@1350,2497.17 1632.83,2497.17 C11.1@1640,2490 ; R2.2@1250,1110 1300,1060 v1(1320,1060) ; R1.2@1250,1210 v1(1330,1210) ; C3.1@1480,1150 1497.76,1132.24 v1(1497.76,1060) U5.8@1497.76,1008.39 ; v1(1640,2560) C11.1@1640,2490 ; v1(1750,2560) R6.2@1750,2490 C11.1@1640,2490 ; C6.1@1814.41,1160.31 1849.69,1160.31 1875,1135 v1(1875,1110) 1875,1102.99 1861.85,1089.84 U2.8@1837.4,1089.84 ; C7.1@1814.41,1280.31 1814.41,1315.59 1783.78,1346.22 v1(1783.78,1370) 1783.78,1390 1794.09,1400.31 U4.5@1828.54,1400.31 ; C5.1@1824.41,940.31 1889.69,940.31 1900,930 v1(1900,910) 1900.55,909.45 U1.14@1900.55,857.08 ; v1(1970,2240) U11.2@2025.87,2240 ; v1(2170,2240) T1.2@2220,2240 ; C10.1@2240,1210 v1(2240,1150) 2240,1136.2 2251.2,1125 U6.1@2291.73,1125
GND: C1.1 C2.1 C3.2 C4.2 C5.2 C6.2 C7.2 C9.2 C10.2 C12.2 C14.2 C16.2 D2.1 D4.1 J2.3 J5.2 R7.1 R8.1 R9.1 R14.1 TP9.1 U1.7 U2.4 U3.2 U4.2 U5.4 U6.4 U8.2 U8.8 U9.10 U9.11@1350,1960 U10.1 U10.2 U10.3 U10.7@850,2090 U11.4 U11.5 | length 2559
  Top Layer w10: J2.3@114,990 v1(220,990) ; U8.2@435,1077.28 435,1115 v1(450,1130) 470,1150 C9.2@470,1190 ; U8.8@485,862.72 485,815 v1(490,810) ; v1(660,2520) D4.1@660,2598.66 ; v1(900,1110) 974.41,1110 979.41,1105 C2.1@984.41,1110 ; v1(900,1210) C1.1@984.41,1210 ; v1(920,970) U3.2@970.28,970 ; v1(930,850) C4.2@994.41,850 ; v1(1290,930) 1291.61,931.61 U5.4@1342.24,931.61 ; v1(1610,700) 1613.54,703.54 U1.7@1668.26,703.54 ; v1(1670,1180) 1680,1180 1699.69,1160.31 C6.2@1734.41,1160.31 ; v1(1670,1280) 1734.09,1280 C7.2@1734.41,1280.31 ; v1(1670,1400) 1670.31,1400.31 U4.2@1720.28,1400.31 ; v1(1682.44,958.19) 1700.31,940.31 C5.2@1744.41,940.31 ; U2.4@1711.42,1030.79 1759.21,1030.79 1775,1046.57 v1(1775,1045) ; v1(2205.06,1360.17) 2205.06,1324.94 C10.2@2240,1290 ; v1(2240,980) 2245,975 U6.4@2291.73,975
  Top Layer w12: U10.3@824.41,2128.39 824.41,2154.41 830,2160 v4@850,2160 ; U10.2@850,2128.39 v4@850,2160 ; v4(850,2180) v4@850,2160 ; U10.1@875.59,2128.39 875.59,2154.41 870,2160 v4@850,2160 ; v1(1010,1800) R9.1@1070,1800 ; v1(1010,1880) C16.2@1078.5,1880 ; v1(1010,1960) R8.1@1070,1960 ; v1(1050,2310) C12.2@1050,2382.91 ; v1(1400,1060) C3.2@1400,1150 ; U9.10@1405.12,1999.37 1419.37,1999.37 v1(1440,2020) ; v1(1650,1860) R14.1@1650,1920 ; R7.1@1860,2490 v1(1860,2560) ; v1(2131.73,2320.18) 2131.73,2309.13 2134.13,2306.73 U11.5@2134.13,2277.4 ; U11.4@2134.13,2202.6 2134.13,2175.87 v1(2145,2165)
  Top Layer w20: D2.1@420,2178.74 477.24,2178.74 480,2181.5 v4(480,2300) ; v4(660,1890) C14.2@732.91,1890
  Top Layer w80: J5.2@130,2208.43 159.69,2178.74 D2.1@420,2178.74
  other v3: 1350,1920.63 1325.39,1960 1374.61,1960 1350,1999.37 828.35,2090 871.65,2090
